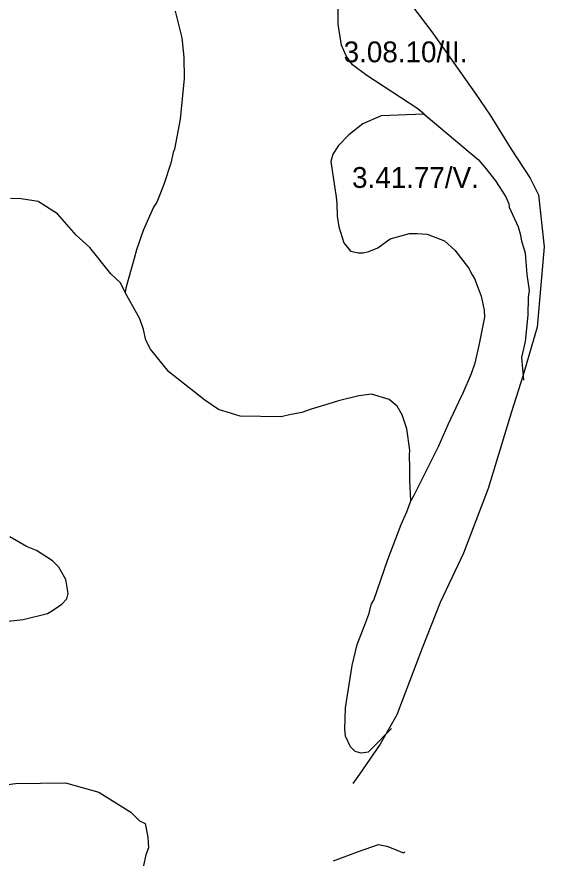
# Model space of a CAD drawing. Extents: x -555509 to -553014, y -1186753 to -1182560.
# Drawn here: x -553520 to -553014, y -1186033 to -1185224 of the extents above; entities that cross this region are included whole.
import ezdxf

# ---------------------------------------------------------------- set-up
doc = ezdxf.new("R2010")
doc.units = 0
doc.layers.add('Level 29', color=7, linetype='Continuous')
doc.layers.add('pěší_tr', color=7, linetype='Continuous')

msp = doc.modelspace()

# ---------------------------------------------------------------- linework, layer by layer
at = {"layer": 'Level 29'}
for points in [[(-553128.94, -1185318), (-553134.88, -1185312.88), (-553184.06, -1185280.63), (-553197.62, -1185270.5), (-553204, -1185262), (-553208.25, -1185251.75), (-553211.62, -1185231.5), (-553211.62, -1185212.75), (-553210.38, -1185187.38), (-553211.62, -1185165.25), (-553218.44, -1185151.38), (-553221.38, -1185145), (-553228.19, -1185122.88), (-553231.56, -1185114.38), (-553242.12, -1185089), (-553246.81, -1185075.38), (-553251.06, -1185060.12), (-553254, -1185053.38), (-553258.83, -1185032.89)], [(-553368.06, -1185219.13), (-553361.69, -1185244.63), (-553360, -1185263.25), (-553359.62, -1185283.63), (-553363.44, -1185322.62), (-553368.94, -1185351.5), (-553370.19, -1185354.88), (-553372.31, -1185365), (-553379.12, -1185385.38), (-553385.88, -1185402.38), (-553388.88, -1185407.38), (-553399, -1185429.5), (-553405.38, -1185448.12), (-553407.5, -1185456.62), (-553415.56, -1185485), (-553416.38, -1185489.25)], [(-553128.94, -1185318), (-553170.06, -1185319.63), (-553187.88, -1185327.25), (-553201.44, -1185337.88), (-553211.19, -1185348), (-553216.69, -1185356.5), (-553218.44, -1185363.25), (-553215, -1185387), (-553213.31, -1185397.25), (-553212.88, -1185404), (-553212.5, -1185415.88), (-553210.75, -1185426), (-553206.12, -1185441.38), (-553199.75, -1185449.38), (-553192.12, -1185451.13), (-553187.44, -1185451.13), (-553181.94, -1185449.75), (-553173.44, -1185446.38), (-553161.62, -1185437.5), (-553142.94, -1185432.38), (-553135.75, -1185432.38), (-553126, -1185433.25), (-553109.44, -1185439.62), (-553099.25, -1185448.5), (-553086.12, -1185465.5), (-553082.75, -1185472.25), (-553080.62, -1185475.62), (-553078.06, -1185482.5), (-553074.25, -1185492.62), (-553071.31, -1185506.25), (-553070.88, -1185513), (-553075.94, -1185538.38), (-553080.19, -1185557.12), (-553083.56, -1185567.25), (-553091.62, -1185585.88), (-553095.88, -1185594.38), (-553106.06, -1185616.38), (-553114.94, -1185636.75), (-553138.69, -1185684.25), (-553141.69, -1185689.38)], [(-553128.94, -1185318), (-553076.81, -1185361.63), (-553069.62, -1185370.13), (-553060.25, -1185382), (-553050.5, -1185397.25), (-553047.56, -1185404), (-553047.12, -1185407.38), (-553038.62, -1185426), (-553036.5, -1185432.88), (-553035.25, -1185439.62), (-553031.88, -1185451.5), (-553030.19, -1185471.88), (-553028.06, -1185487.13), (-553028.88, -1185493.88), (-553029.31, -1185510.88), (-553031.88, -1185536.25), (-553035.25, -1185551.5), (-553033.54, -1185573.41)], [(-553416.38, -1185489.25), (-553420.62, -1185479.88), (-553430, -1185471.38), (-553450.31, -1185446), (-553463.5, -1185434.13), (-553481.25, -1185413.75), (-553499.94, -1185401.88), (-553516.06, -1185399.38), (-553526.62, -1185398.88)], [(-553141.69, -1185689.38), (-553142.5, -1185669.38), (-553142.5, -1185657.5), (-553142.94, -1185645.62), (-553142.5, -1185640.63), (-553145.5, -1185620.25), (-553150.12, -1185606.62), (-553154.81, -1185598.25), (-553162.44, -1185591.88), (-553179.38, -1185586.75), (-553191.69, -1185588.5), (-553211.19, -1185593.12), (-553221.38, -1185596.5), (-553237.5, -1185601.12), (-553246.38, -1185604.5), (-553258.25, -1185606.62), (-553266.31, -1185608.75), (-553305.75, -1185608), (-553326.5, -1185601.62), (-553339.69, -1185592.63), (-553374.44, -1185565.5), (-553391.81, -1185543.5), (-553396.5, -1185535), (-553398.62, -1185524.88), (-553402, -1185514.63), (-553416.38, -1185489.25)], [(-553160.22, -1185907.95), (-553179, -1185926.75), (-553182.81, -1185930.62), (-553189.56, -1185931.5), (-553195.06, -1185930.12), (-553199.75, -1185925.5), (-553204.44, -1185915.38), (-553205.25, -1185908.5), (-553204.44, -1185888.25), (-553198.06, -1185847.5), (-553193.38, -1185827.13), (-553185.75, -1185808.5), (-553181.94, -1185798.25), (-553179.38, -1185788.12), (-553177.31, -1185784.75), (-553163.69, -1185745.75), (-553151, -1185711.88), (-553145.5, -1185700), (-553141.69, -1185689.38)], [(-553534.69, -1185805.5), (-553514.38, -1185803.38), (-553491, -1185797.5), (-553487.19, -1185795.38), (-553477.06, -1185788.5), (-553472.38, -1185783.5), (-553471.12, -1185778.38), (-553473.25, -1185764.88), (-553480, -1185753), (-553485.94, -1185747), (-553501.62, -1185736.88), (-553510.94, -1185733), (-553527.06, -1185723.75)], [(-553597, -1185943.25), (-553583.88, -1185954.38), (-553577.5, -1185956.88), (-553558.44, -1185961.5), (-553533.88, -1185962.38), (-553521.56, -1185960.75), (-553473.62, -1185960.25), (-553441.44, -1185969.13), (-553410.88, -1185988.25), (-553402.44, -1185996.75), (-553396.88, -1185999.25), (-553394.38, -1186012.38), (-553393.94, -1186022.62), (-553396.5, -1186029.38), (-553398.62, -1186039.5), (-553399, -1186042.5), (-553403.25, -1186053.13), (-553410.06, -1186063.25), (-553430.81, -1186083.62), (-553447.17, -1186102.56), (-553464.42, -1186123.36)]]:
    msp.add_lwpolyline(points, dxfattribs=at)
at = {"layer": 'pěší_tr'}
for points in [[(-553146.71, -1185205.27), (-553121.36, -1185238.7), (-553079.98, -1185297.62), (-553065.59, -1185318.86), (-553045.18, -1185351.47), (-553026.95, -1185379.43), (-553018.86, -1185395.46), (-553013.52, -1185445.2), (-553020.37, -1185522.48), (-553034.07, -1185569.48), (-553045.04, -1185603.87), (-553067.51, -1185677.59), (-553091.21, -1185739.52), (-553113.55, -1185787.07), (-553130.68, -1185830.91), (-553155.07, -1185894.9), (-553171.23, -1185923.13), (-553190.97, -1185951.77), (-553197.41, -1185960.75)], [(-553215.91, -1186035.21), (-553192.13, -1186026.03), (-553172.61, -1186019.45), (-553164.66, -1186020.89), (-553152.53, -1186025.76), (-553148.9, -1186027.33), (-553147.18, -1186026.26)]]:
    msp.add_lwpolyline(points, dxfattribs=at)

# ---------------------------------------------------------------- texts
at = {"layer": 'Level 29'}
for s, p in [('3.08.10/II.', (-553206.26, -1185268.1)), ('3.41.77/V.', (-553198.2, -1185388.74))]:
    msp.add_text(s, height=20, dxfattribs=at).set_placement(p)

doc.saveas('drawing.dxf')
